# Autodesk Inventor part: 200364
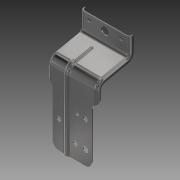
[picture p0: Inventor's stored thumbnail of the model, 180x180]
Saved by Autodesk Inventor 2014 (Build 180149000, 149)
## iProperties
Created: 2007-12
Part Number: 200364
Document SubType Name: Modeling
Designer: TH
Density: 7.85 g/cm^3
Mass: 153.679 g
Surface Area: 267.655 cm^2
Volume: 19.5769 cm^3
Material: Steel
Description: POWER MOUNTING BRACKET
Appearance: Steel - Polished
Component Category: Lower Component
Author: TH
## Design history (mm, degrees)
sketch "Sketch2"
  geometry: L1 (0, 0)-(0, -151.25); L2 (0, -151.25)-(-55.25, -151.25); L3 (-55.25, -151.25)-(-55.25, -47.742); L4 (0, 0)-(-6.3, 0); L5 (-6.3, 0)-(-6.3, -21.951); L6 (-10.26, -26.842)-(-44.161, -34.048); A1 r 5 centre (-11.3, -21.951) between (-10.26, -26.842) and (-6.3, -21.951); A2 r 14 centre (-41.25, -47.742) between (-44.161, -34.048) and (-55.25, -47.742); 1 further point
  constraints: 12 end point, 4 point on circle, 4 tangent, 3 perpendicular, 2 centre point, 2 point on line, 1 parallel, 1 vertical
  dimensions: "d0" = 102 deg angle of L6 L5; "d1" = 6.3 distance between parallel lines of L1 L5; "d2" = 26 distance of L4.end point (-6.3, -26); "d3" = 151.25 distance of L1.start L1.end; "d4" = 55.25 distance between parallel lines of L1 L3; "d5" = 5 radius of A1; "d6" = 14 radius of A2
extrude "Extrusion1" new body sketch "Sketch2" stored distance "d7" = 73.7; taper "d8" = 0 deg
fillet "Fillet1" dims "d9" = 5
workplane "Work Plane1"
sketch "Sketch3"
  geometry: L1 (-19.553, -28.817)-(-20.073, -26.372); L2 (-20.073, -26.372)-(-43.931, -31.443); L3 (-55.25, -151.25)-(-57, -151.25); L4 (-57, -151.25)-(-57, -47.582); L5 (-6.3, -21.951)-(-6.3, 0) reference; L6 (-6.3, 0)-(0, 0) reference; L7 (0, 0)-(0, -151.25) reference; L8 (0, -151.25)-(-55.25, -151.25) reference; L9 (-55.25, -151.25)-(-55.25, -47.742) reference; L10 (-44.161, -34.048)-(-10.26, -26.842) reference; A1 r 16.5 centre (-40.5, -47.582) between (-43.931, -31.443) and (-57, -47.582); A2 r 14 centre (-41.25, -47.742) between (-44.161, -34.048) and (-55.25, -47.742) reference; A3 r 5 centre (-11.3, -21.951) between (-10.26, -26.842) and (-6.3, -21.951) reference
  constraints: 8 end point, 2 parallel, 2 perpendicular, 2 point on circle, 2 tangent, 1 centre point, 1 point on line
  dimensions: "d12" = 16.5 radius of A1; "d16" = 2.5 distance between parallel lines of L10 L2; "d17" = 1.75 distance between parallel lines of L9 L4; "d18" = 9.5 distance from line of A3.centre L1
extrude "Extrusion2" join sketch "Sketch3" stored distance "d13" = 4; taper "d14" = 0 deg
fillet "Fillet2" dims "d19" = 2
fillet "Fillet3" dims "d20" = 3.25
shell "Shell1" dims "d21" = 1.52088
sketch "Sketch4"
  geometry: L1 (38.938, -43.121)-(31.733, -9.221) reference; L2 (151.25, -50.25)-(47.742, -50.25) reference; L3 (151.25, 0)-(151.25, -50.25) reference; L4 (0, 0)-(151.25, 0) reference; L5 (31.733, -9.221)-(33.004, -8.951); L6 (33.004, -8.951)-(40.21, -42.851); L7 (47.742, -48.95)-(151.25, -48.95); L8 (21.951, 0)-(151.25, 0); L9 (151.25, 0)-(151.25, -48.95); A1 r 10 centre (21.951, -11.3) between (31.733, -9.221) and (21.951, -1.3) reference; A2 r 9 centre (47.742, -41.25) between (38.938, -43.121) and (47.742, -50.25) reference; A3 r 11.3 centre (21.951, -11.3) between (33.004, -8.951) and (21.951, 0); A4 r 7.7 centre (47.742, -41.25) between (40.21, -42.851) and (47.742, -48.95)
  constraints: 10 end point, 5 tangent, 4 point on circle, 2 centre point, 2 coincident, 2 collinear, 2 perpendicular, 2 point on line, 1 parallel
extrude "Extrusion3" cut sketch "Sketch4" stored distance "d22" = 4; taper "d23" = 0 deg
sketch "Sketch5"
  geometry: L1 (0, 0)-(0, 103.508) reference; L2 (28.876, -14.331)-(28.55, -14.331) reference; L3 (23.635, -11.692)-(5, -11.692) reference; L4 (0, -4.659)-(0, 0) reference; L5 (0, 0)-(1.521, 0) reference; L6 (1.521, 103.508)-(1.521, 0) reference; L7 (0, 103.508)-(1.521, 103.508) reference; L8 (0, 0)-(0, 103.508) reference; L9 (68.7, -11.692)-(33.791, -11.692) reference; L10 (73.7, 0)-(73.7, -4.659) reference; L11 (72.179, 0)-(73.7, 0) reference; L12 (72.179, 0)-(72.179, 103.508) reference; L13 (72.179, 103.508)-(73.7, 103.508) reference; L14 (73.7, 103.508)-(73.7, 0) reference; L15 (1.521, 0)-(1.521, -4.659) reference; L16 (5, -9.82)-(23.655, -9.82) reference; L17 (28.526, -12.528)-(28.9, -12.528) reference; L18 (33.771, -9.82)-(68.7, -9.82) reference; L19 (72.179, -4.659)-(72.179, 0) reference; L20 (0, 103.508)-(7.25, 103.508); L21 (0, 16.937)-(0, 103.508); L22 (7.25, 103.508)-(7.25, 25.765); A1 r 9 centre (-1.75, 25.765) between (0, 16.937) and (7.25, 25.765); 5 further points
  constraints: 6 end point, 2 perpendicular, 2 point on circle, 1 centre point, 1 collinear, 1 tangent, 12 other
  dimensions: "d27" = 9 radius of A1; "d28" = 7.25 distance between parallel lines of L1 L22; "d29" = 77.74342 distance from line of L20 A1.centre
extrude "Extrusion4" cut sketch "Sketch5" stored distance "d30" = 4; taper "d31" = 0 deg
mirror "Mirror1"
fillet "Fillet4" dims "d32" = 6.3
fillet "Fillet5" dims "d33" = 10
sketch "Sketch6"
  geometry: L1 (0, -181.5)-(0, 30.25) reference; L2 (-51.6, 0)-(51.595, 0) reference; 9 further points
  constraints: 1 point on line
  dimensions: "d34" = 7.865 distance from line of point (24, -7.865) L2; "d35" = 9.795 distance from line of L2 point (0, -9.795); "d36" = 7.865 distance from line of L2 point (-24, -7.865); "d37" = 24 distance from line of L1 point (-24, -7.865); "d38" = 24 distance from line of point (24, -7.865) L1; "d39" = 7.43751 distance from line of L1 point (-7.438, -89.802); "d40" = 19.93751 distance from line of L1 point (-19.938, -89.802); "d41" = 20.06249 distance from line of L1 point (20.062, -109.802); "d42" = 4.43751 distance from line of L1 point (-4.438, -129.802); "d43" = 19.93751 distance from line of point (-19.938, -129.802) L1; "d44" = 89.80223 distance from line of point (-7.438, -89.802) L2; "d45" = 89.80223 distance from line of L2 point (-19.938, -89.802); "d46" = 129.80223 distance from line of L2 point (-19.938, -129.802); "d47" = 129.80223 distance from line of L2 point (-4.438, -129.802); "d48" = 109.80223 distance from line of L2 point (20.062, -109.802)
hole "Hole1" sketch "Sketch6" diameter "d49" = 6.7; stored, may be unused: countersink angle "d53" = 90 deg, drill point angle "d55" = 118 deg; dims "d50" = 6, "d51" = 4, "d52" = 2, "d54" = 8
hole "Hole2" sketch "Sketch6" diameter "d56" = 8; stored, may be unused: countersink angle "d60" = 90 deg, drill point angle "d62" = 118 deg; dims "d57" = 6, "d58" = 4, "d59" = 2, "d61" = 8
hole "Hole3" sketch "Sketch6" diameter "d63" = 5; stored, may be unused: countersink angle "d67" = 90 deg, drill point angle "d69" = 118 deg; dims "d64" = 6, "d65" = 4, "d66" = 2, "d68" = 8
hole "Hole4" sketch "Sketch6" diameter "d70" = 11.45; stored, may be unused: countersink angle "d74" = 90 deg, drill point angle "d76" = 118 deg; dims "d71" = 6, "d72" = 4, "d73" = 2, "d75" = 8
body "Solid1"
node "Project Cut Edges2"
node "Project Cut Edges3"
other parameters: "d15" = -8.137, "d24" = 18, "d26" = 7.25
